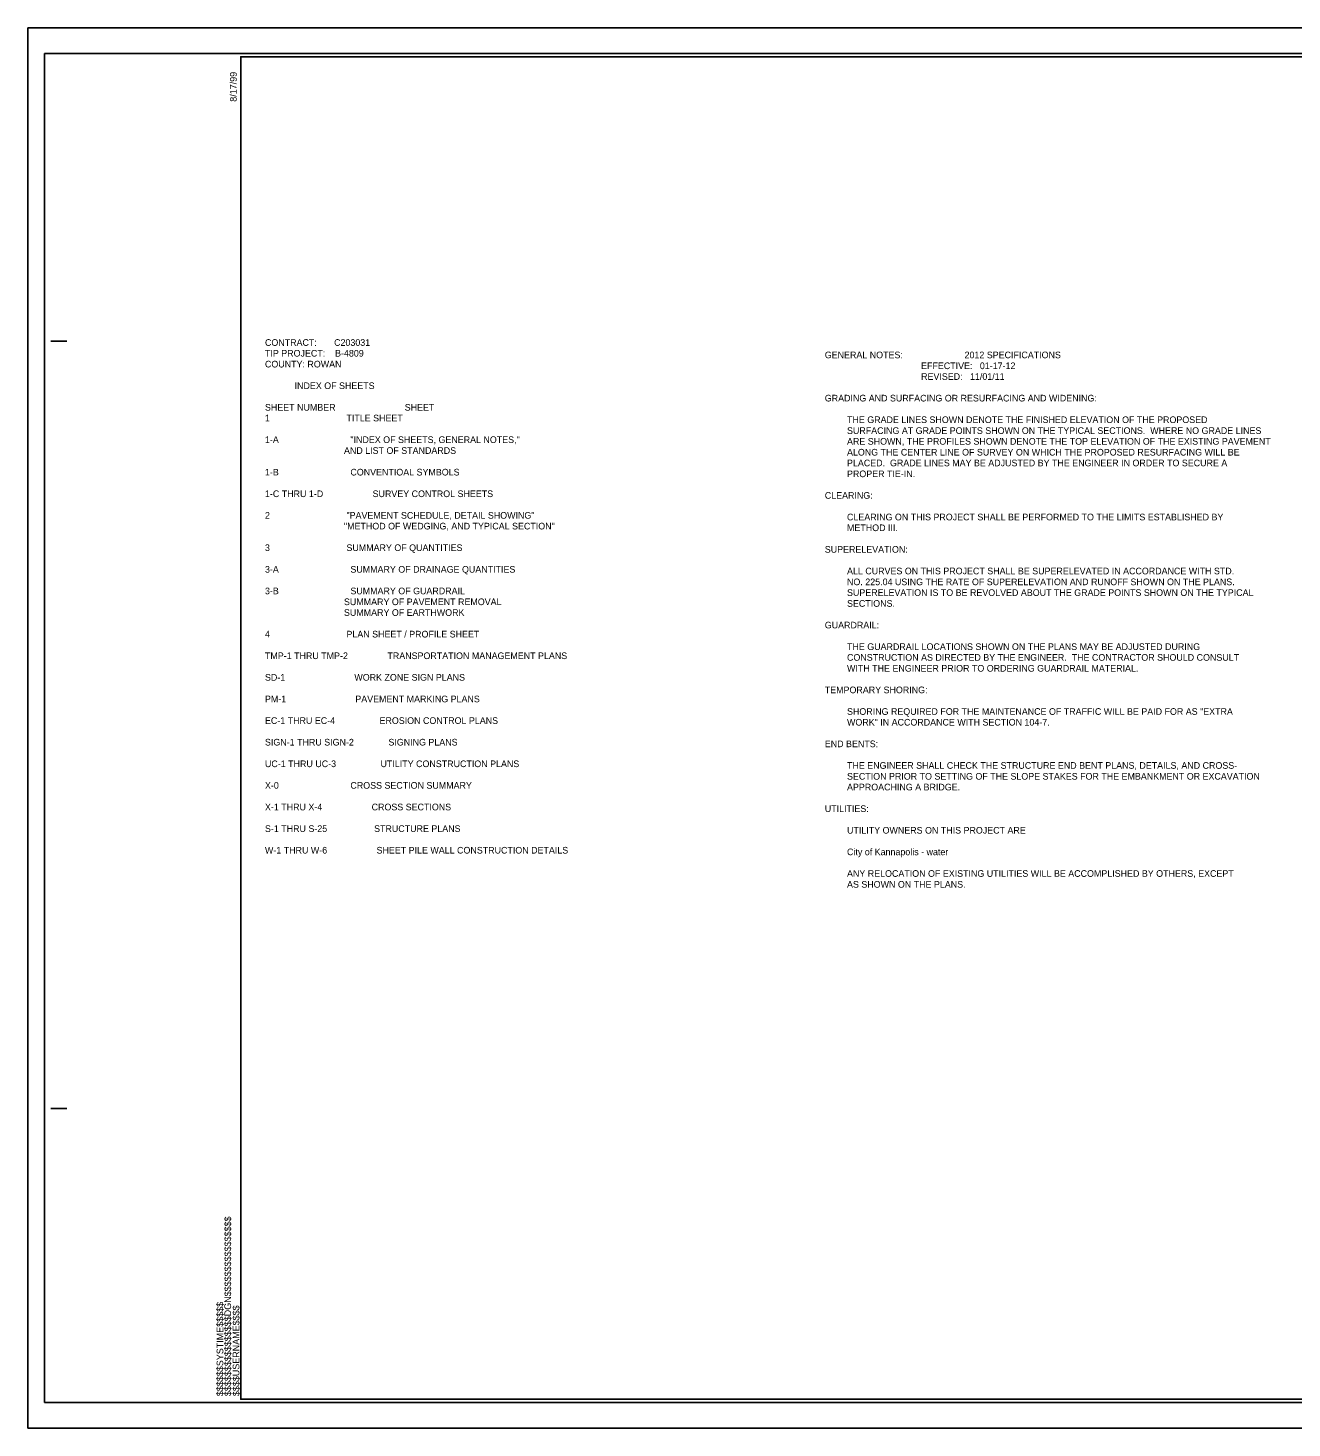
# Model space of a CAD drawing. Extents: x 9834 to 11517, y 9978 to 11072.
# Drawn here: x 9834 to 10822, y 9978 to 11072 of the extents above; entities that cross this region are included whole.
import ezdxf

# ---------------------------------------------------------------- set-up
doc = ezdxf.new("R2010")
doc.units = 0
for name, color, linetype in [('Default', 7, 'Continuous'), ('Sheet Cutting Line CELL', 7, 'Continuous'), ('Sheet Plan CELL', 7, 'Continuous'), ('Sheet Plot Border Inside CELL', 7, 'Continuous'), ('Sheet Plot Border Outside CELL', 7, 'Continuous')]:
    doc.layers.add(name, color=color, linetype=linetype)

msp = doc.modelspace()

# ---------------------------------------------------------------- linework, layer by layer
at = {"layer": 'Sheet Cutting Line CELL'}
for p, q in [((11517, 11072.5), (9833.5, 11072.5)), ((9833.5, 11072.5), (9833.5, 9977.5)), ((9833.5, 9977.5), (11517, 9977.5))]:
    msp.add_line(p, q, dxfattribs=at)
at = {"layer": 'Sheet Plan CELL'}
for p, q in [((10000, 11050), (10000, 11050)), ((9851.5, 10827.5), (9864, 10827.5)), ((9851.5, 10227.5), (9864, 10227.5)), ((10000, 10000), (10000, 10000))]:
    msp.add_line(p, q, dxfattribs=at)
msp.add_lwpolyline([(11500, 11050), (10000, 11050), (10000, 10000), (11500, 10000)], close=True, dxfattribs=at)
at = {"layer": 'Sheet Plot Border Inside CELL'}
msp.add_lwpolyline([(9846.5, 9997.5), (11512.5, 9997.5), (11512.5, 11052.5), (9846.5, 11052.5)], close=True, dxfattribs=at)
at = {"layer": 'Sheet Plot Border Outside CELL'}
msp.add_lwpolyline([(9833.5, 9977.5), (11517, 9977.5), (11517, 11072.5), (9833.5, 11072.5)], close=True, dxfattribs=at)

# ---------------------------------------------------------------- texts
at = {"layer": 'Default'}
for s, p in [('TIP PROJECT:    B-4809                  ', (10018.9, 10815.5)), ('CONTRACT:       C203031                 ', (10018.9, 10823.9)), ('GENERAL NOTES:                         2012 SPECIFICATIONS', (10456.9, 10814.2)), ('COUNTY: ROWAN                   ', (10018.9, 10807)), ('                                       EFFECTIVE:   01-17-12', (10456.9, 10805.7)), ('                                       REVISED:   11/01/11', (10456.9, 10797.3)), ('            INDEX OF SHEETS                             ', (10018.9, 10790.1)), ('SHEET NUMBER                            SHEET', (10018.9, 10773.2)), ('GRADING AND SURFACING OR RESURFACING AND WIDENING:  ', (10456.9, 10780.4)), ('1                               TITLE SHEET', (10018.9, 10764.8)), ('         THE GRADE LINES SHOWN DENOTE THE FINISHED ELEVATION OF THE PROPOSED ', (10456.9, 10763.5)), ('1-A                             "INDEX OF SHEETS, GENERAL NOTES,"', (10018.9, 10747.9)), ('         SURFACING AT GRADE POINTS SHOWN ON THE TYPICAL SECTIONS.  WHERE NO GRADE LINES ', (10456.9, 10755)), ('                                AND LIST OF STANDARDS', (10018.9, 10739.4)), ('         ARE SHOWN, THE PROFILES SHOWN DENOTE THE TOP ELEVATION OF THE EXISTING PAVEMENT ', (10456.9, 10746.6)), ('         ALONG THE CENTER LINE OF SURVEY ON WHICH THE PROPOSED RESURFACING WILL BE ', (10456.9, 10738.1)), ('         PLACED.  GRADE LINES MAY BE ADJUSTED BY THE ENGINEER IN ORDER TO SECURE A ', (10456.9, 10729.7)), ('1-B                             CONVENTIOAL SYMBOLS', (10018.9, 10722.5)), ('         PROPER TIE-IN.  ', (10456.9, 10721.2)), ('1-C THRU 1-D                    SURVEY CONTROL SHEETS', (10018.9, 10705.6)), ('CLEARING:  ', (10456.9, 10704.3)), ('2                               "PAVEMENT SCHEDULE, DETAIL SHOWING"', (10018.9, 10688.7)), ('         CLEARING ON THIS PROJECT SHALL BE PERFORMED TO THE LIMITS ESTABLISHED BY ', (10456.9, 10687.4)), ('                                "METHOD OF WEDGING, AND TYPICAL SECTION"', (10018.9, 10680.3)), ('         METHOD III.', (10456.9, 10679)), ('3                               SUMMARY OF QUANTITIES', (10018.9, 10663.4)), ('SUPERELEVATION:  ', (10456.9, 10662.1)), ('3-A                             SUMMARY OF DRAINAGE QUANTITIES', (10018.9, 10646.5)), ('         ALL CURVES ON THIS PROJECT SHALL BE SUPERELEVATED IN ACCORDANCE WITH STD. ', (10456.9, 10645.2)), ('3-B                             SUMMARY OF GUARDRAIL', (10018.9, 10629.6)), ('         SUPERELEVATION IS TO BE REVOLVED ABOUT THE GRADE POINTS SHOWN ON THE TYPICAL ', (10456.9, 10628.3)), ('         NO. 225.04 USING THE RATE OF SUPERELEVATION AND RUNOFF SHOWN ON THE PLANS.', (10456.9, 10636.7)), ('                                SUMMARY OF PAVEMENT REMOVAL', (10018.9, 10621.1)), ('         SECTIONS.  ', (10456.9, 10619.8)), ('                                SUMMARY OF EARTHWORK', (10018.9, 10612.7)), ('4                               PLAN SHEET / PROFILE SHEET', (10018.9, 10595.8)), ('GUARDRAIL:  ', (10456.9, 10602.9)), ('         THE GUARDRAIL LOCATIONS SHOWN ON THE PLANS MAY BE ADJUSTED DURING ', (10456.9, 10586)), ('TMP-1 THRU TMP-2                TRANSPORTATION MANAGEMENT PLANS', (10018.9, 10578.9)), ('         CONSTRUCTION AS DIRECTED BY THE ENGINEER.  THE CONTRACTOR SHOULD CONSULT', (10456.9, 10577.6)), ('SD-1                            WORK ZONE SIGN PLANS', (10018.9, 10562)), ('         WITH THE ENGINEER PRIOR TO ORDERING GUARDRAIL MATERIAL.', (10456.9, 10569.1)), ('TEMPORARY SHORING:  ', (10456.9, 10552.2)), ('PM-1                            PAVEMENT MARKING PLANS', (10018.9, 10545.1)), ('         SHORING REQUIRED FOR THE MAINTENANCE OF TRAFFIC WILL BE PAID FOR AS "EXTRA ', (10456.9, 10535.3)), ('EC-1 THRU EC-4                  EROSION CONTROL PLANS', (10018.9, 10528.2)), ('         WORK" IN ACCORDANCE WITH SECTION 104-7.  ', (10456.9, 10526.9)), ('SIGN-1 THRU SIGN-2              SIGNING PLANS', (10018.9, 10511.3)), ('END BENTS:  ', (10456.9, 10510)), ('UC-1 THRU UC-3                  UTILITY CONSTRUCTION PLANS', (10018.9, 10494.4)), ('         THE ENGINEER SHALL CHECK THE STRUCTURE END BENT PLANS, DETAILS, AND CROSS-', (10456.9, 10493.1)), ('X-0                             CROSS SECTION SUMMARY', (10018.9, 10477.5)), ('         APPROACHING A BRIDGE.  ', (10456.9, 10476.2)), ('         SECTION PRIOR TO SETTING OF THE SLOPE STAKES FOR THE EMBANKMENT OR EXCAVATION ', (10456.9, 10484.6)), ('X-1 THRU X-4                    CROSS SECTIONS', (10018.9, 10460.6)), ('UTILITIES:  ', (10456.9, 10459.3)), ('S-1 THRU S-25                   STRUCTURE PLANS', (10018.9, 10443.7)), ('         UTILITY OWNERS ON THIS PROJECT ARE ', (10456.9, 10442.4)), ('W-1 THRU W-6                    SHEET PILE WALL CONSTRUCTION DETAILS', (10018.9, 10426.8)), ('         City of Kannapolis - water', (10456.9, 10425.5)), ('         ANY RELOCATION OF EXISTING UTILITIES WILL BE ACCOMPLISHED BY OTHERS, EXCEPT ', (10456.9, 10408.6)), ('         AS SHOWN ON THE PLANS.  ', (10456.9, 10400.1))]:
    msp.add_text(s, height=5.2, dxfattribs=at).set_placement(p)
at = {"layer": 'Sheet Plan CELL'}
for s, p in [('8/17/99', (9996.8, 11014.8)), ('$$$$$$$$$$$$$$$$DGN$$$$$$$$$$$$$$$$', (9992.4, 10002.4)), ('$$$$$$SYSTIME$$$$$', (9986.3, 10002.4)), ('$$$$USERNAME$$$$', (9998.9, 10002.4))]:
    msp.add_text(s, height=5.25, rotation=90, dxfattribs=at).set_placement(p)

doc.saveas('drawing.dxf')
